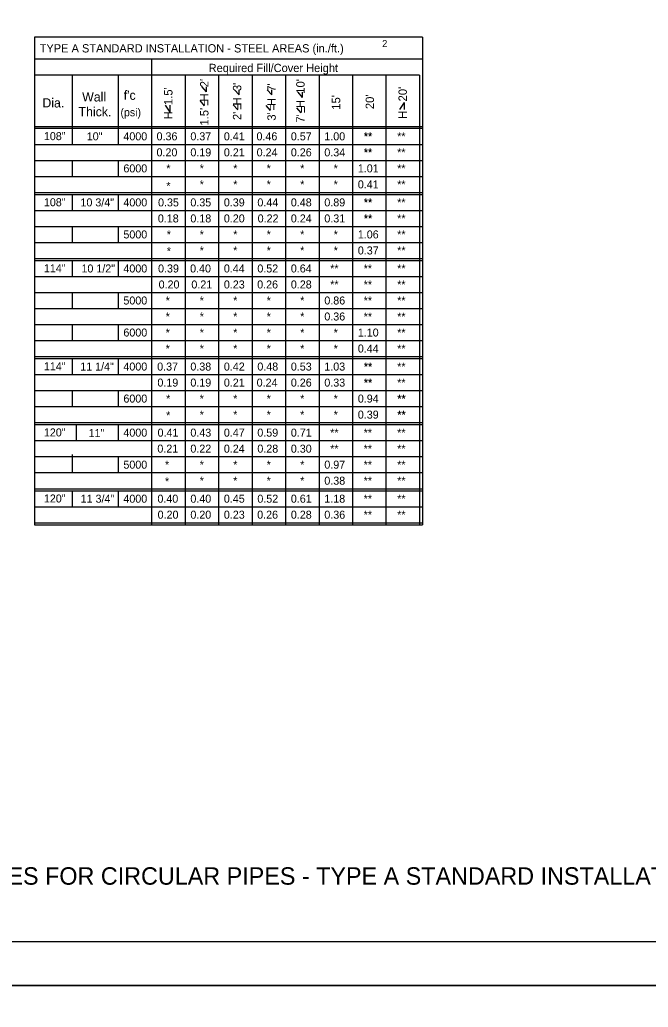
# Model space of a CAD drawing. Extents: x -22562 to -18409, y 3991 to 7171.
# Drawn here: x -20171.7 to -19955.7, y 5765.9 to 6105.3 of the extents above; entities that cross this region are included whole.
import ezdxf

# ---------------------------------------------------------------- set-up
doc = ezdxf.new("R2010")
doc.units = 0
for name, color, linetype in [('1', 7, 'Continuous'), ('2', 7, 'Continuous'), ('3', 7, 'Continuous'), ('4', 7, 'Continuous'), ('PLT-BNDY', 7, 'Continuous')]:
    doc.layers.add(name, color=color, linetype=linetype)

msp = doc.modelspace()

# ---------------------------------------------------------------- linework, layer by layer
at = {"layer": '1'}
for p, q in [((-20107.5, 6080.55), (-20109.07, 6082.32)), ((-20107.5, 6080.55), (-20107.5, 6082.3)), ((-20096.32, 6079.45), (-20097.89, 6081.22)), ((-20096.32, 6079.45), (-20096.32, 6081.21)), ((-20085.03, 6079.51), (-20086.6, 6081.27)), ((-20085.03, 6079.51), (-20085.03, 6081.26)), ((-20074.46, 6078.62), (-20076.02, 6080.38)), ((-20074.46, 6078.62), (-20074.46, 6080.37)), ((-20108.16, 6075.74), (-20109.72, 6077.51)), ((-20096.78, 6074.31), (-20098.34, 6076.08)), ((-20039.54, 6076.83), (-20041.11, 6074.41)), ((-20039.54, 6076.83), (-20039.54, 6074.43)), ((-20119.99, 6073.55), (-20121.55, 6075.97)), ((-20119.99, 6073.55), (-20119.99, 6075.96)), ((-20085.49, 6074.09), (-20087.05, 6075.86)), ((-20074.91, 6073.26), (-20076.47, 6075.02))]:
    msp.add_line(p, q, dxfattribs=at)
at = {"layer": '2'}
for p, q in [((-20166.67, 6099.37), (-20166.67, 5931.73)), ((-20033.26, 6099.37), (-20166.67, 6099.37)), ((-20033.26, 6099.37), (-20033.26, 5931.73)), ((-20033.26, 6091.8), (-20166.67, 6091.8)), ((-20126.39, 6091.8), (-20126.39, 5931.73)), ((-20034.3, 6086.29), (-20166.67, 6086.29)), ((-20153.72, 6086.29), (-20153.72, 6062.48)), ((-20137.9, 6086.29), (-20137.9, 6062.48)), ((-20114.88, 6086.29), (-20114.88, 5931.73)), ((-20103.36, 6086.29), (-20103.36, 5931.73)), ((-20091.85, 6086.29), (-20091.85, 5931.73)), ((-20080.34, 6086.29), (-20080.34, 5931.73)), ((-20068.83, 6086.29), (-20068.83, 5931.73)), ((-20057.32, 6086.29), (-20057.32, 5931.73)), ((-20045.81, 6086.29), (-20045.81, 5931.73)), ((-20034.3, 6086.29), (-20034.3, 5931.73)), ((-20166.67, 6068.67), (-20033.26, 6068.67)), ((-20166.67, 6067.99), (-20033.26, 6067.99)), ((-20153.72, 6067.99), (-20153.72, 6062.48)), ((-20137.9, 6067.99), (-20137.9, 6062.48)), ((-20166.67, 6062.48), (-20033.26, 6062.48)), ((-20166.67, 6056.98), (-20033.26, 6056.98)), ((-20153.72, 6056.98), (-20153.72, 6051.47)), ((-20137.9, 6056.98), (-20137.9, 6051.47)), ((-20166.67, 6051.47), (-20033.26, 6051.47)), ((-20166.67, 6045.97), (-20033.26, 6045.97)), ((-20166.67, 6045.97), (-20033.26, 6045.97)), ((-20166.67, 6045.28), (-20033.26, 6045.28)), ((-20153.72, 6045.28), (-20153.72, 6039.77)), ((-20137.9, 6045.28), (-20137.9, 6039.77)), ((-20166.67, 6039.77), (-20033.26, 6039.77)), ((-20166.67, 6034.27), (-20033.26, 6034.27)), ((-20153.72, 6034.27), (-20153.72, 6028.76)), ((-20137.9, 6034.27), (-20137.9, 6028.76)), ((-20166.67, 6028.76), (-20033.26, 6028.76)), ((-20166.67, 6023.26), (-20033.26, 6023.26)), ((-20166.67, 6023.26), (-20033.26, 6023.26)), ((-20166.67, 6022.57), (-20033.26, 6022.57)), ((-20153.72, 6022.57), (-20153.72, 6017.07)), ((-20137.9, 6022.57), (-20137.9, 6017.07)), ((-20166.67, 6017.07), (-20033.26, 6017.07)), ((-20166.67, 6011.56), (-20033.26, 6011.56)), ((-20153.72, 6011.56), (-20153.72, 6006.05)), ((-20137.9, 6011.56), (-20137.9, 6006.05)), ((-20166.67, 6006.05), (-20033.26, 6006.05)), ((-20166.67, 6000.55), (-20033.26, 6000.55)), ((-20153.72, 6000.55), (-20153.72, 5995.04)), ((-20137.9, 6000.55), (-20137.9, 5995.04)), ((-20166.67, 5995.04), (-20033.26, 5995.04)), ((-20166.67, 5989.54), (-20033.26, 5989.54)), ((-20166.67, 5989.54), (-20033.26, 5989.54)), ((-20166.67, 5988.85), (-20033.26, 5988.85)), ((-20153.72, 5988.85), (-20153.72, 5983.35)), ((-20137.9, 5988.85), (-20137.9, 5983.35)), ((-20166.67, 5983.35), (-20033.26, 5983.35)), ((-20166.67, 5977.84), (-20033.26, 5977.84)), ((-20153.72, 5977.84), (-20153.72, 5972.33)), ((-20137.9, 5977.84), (-20137.9, 5972.33)), ((-20166.67, 5972.33), (-20033.26, 5972.33)), ((-20166.67, 5966.83), (-20033.26, 5966.83)), ((-20166.67, 5966.14), (-20033.26, 5966.14)), ((-20152.29, 5966.14), (-20152.29, 5960.64)), ((-20137.9, 5966.14), (-20137.9, 5960.64)), ((-20166.67, 5960.64), (-20033.26, 5960.64)), ((-20166.67, 5955.13), (-20033.26, 5955.13)), ((-20153.72, 5955.82), (-20153.72, 5949.63)), ((-20137.9, 5955.13), (-20137.9, 5949.63)), ((-20166.67, 5949.63), (-20033.26, 5949.63)), ((-20166.67, 5944.12), (-20033.26, 5944.12)), ((-20166.67, 5943.43), (-20033.26, 5943.43)), ((-20153.72, 5943.43), (-20153.72, 5937.93)), ((-20137.9, 5943.43), (-20137.9, 5937.93)), ((-20166.67, 5937.93), (-20033.26, 5937.93)), ((-20166.67, 5932.42), (-20033.26, 5932.42)), ((-20166.67, 5932.42), (-20033.26, 5932.42)), ((-20166.67, 5931.73), (-20033.26, 5931.73)), ((-19558.85, 5788.37), (-20344.85, 5788.37))]:
    msp.add_line(p, q, dxfattribs=at)
at = {"layer": 'PLT-BNDY'}
for points in [[(-20384.85, 6367.37), (-19543.85, 6367.37), (-19543.85, 5773.37), (-20384.85, 5773.37)], [(-20384.85, 5773.37), (-19543.85, 5773.37), (-19543.85, 5179.37), (-20384.85, 5179.37)]]:
    msp.add_lwpolyline(points, close=True, dxfattribs=at)

# ---------------------------------------------------------------- texts
at = {"layer": '1'}
for s, height, p in [("f'c", 3.172, (-20135.95, 6077.78)), ('Thick.', 3.172, (-20151.48, 6072.12)), ('(psi)', 2.719, (-20137.07, 6072.14)), ('108"', 2.751, (-20163.39, 6063.92)), ('108"', 2.751, (-20163.39, 6041.21)), ('114"', 2.751, (-20163.39, 6018.51)), ('114"', 2.751, (-20163.39, 5984.79)), ('120"', 2.751, (-20163.39, 5962.08)), ('**', 2.751, (-20064.99, 5962.01)), ('**', 2.751, (-20053.48, 5962.01)), ('**', 2.751, (-20041.97, 5962.01)), ('**', 2.751, (-20064.99, 5956.5)), ('**', 2.751, (-20053.48, 5956.5)), ('**', 2.751, (-20041.97, 5956.5)), ('**', 2.751, (-20053.48, 5951)), ('**', 2.751, (-20041.97, 5951)), ('**', 2.751, (-20053.48, 5945.49)), ('**', 2.751, (-20041.97, 5945.49)), ('120"', 2.751, (-20163.39, 5939.37)), ('**', 2.751, (-20053.48, 5939.3)), ('**', 2.751, (-20041.97, 5939.3)), ('**', 2.751, (-20053.48, 5933.8)), ('**', 2.751, (-20041.97, 5933.8))]:
    msp.add_text(s, height=height, dxfattribs=at).set_placement(p)
for s, height, p in [("20'", 2.883, (-20049.93, 6074.58)), ('=', 2.88, (-20106.21, 6075.71)), ('=', 2.88, (-20094.83, 6074.28)), ('=', 2.88, (-20083.54, 6074.07)), ("15'", 2.883, (-20061.54, 6074.38)), ('=', 2.88, (-20072.96, 6073.23))]:
    msp.add_text(s, height=height, rotation=90, dxfattribs=at).set_placement(p)
at = {"layer": '2'}
for s, height, p in [('TYPE A STANDARD INSTALLATION - STEEL AREAS (in./ft.)', 2.8357, (-20164.84, 6094.07)), ('2', 2.42, (-20047.15, 6095.91)), ('Required Fill/Cover Height', 2.8357, (-20106.76, 6087.32)), ('DESIGN TABLES FOR CIRCULAR PIPES - TYPE A STANDARD INSTALLATION', 6, (-20228.97, 5807.99))]:
    msp.add_text(s, height=height, dxfattribs=at).set_placement(p)
at = {"layer": '3'}
for s, height, p in [('0.36', 2.753, (-20124.66, 6063.86)), ('0.37', 2.753, (-20113.04, 6063.86)), ('0.41', 2.753, (-20101.53, 6063.86)), ('0.46', 2.753, (-20090.32, 6063.86)), ('0.57', 2.753, (-20078.51, 6063.86)), ('1.00', 2.753, (-20067, 6063.86)), ('**', 2.751, (-20053.47, 6063.86)), ('**', 2.753, (-20053.35, 6063.86)), ('**', 2.751, (-20041.96, 6063.86)), ('0.20', 2.753, (-20124.68, 6058.35)), ('0.19', 2.753, (-20113.04, 6058.35)), ('0.21', 2.753, (-20101.53, 6058.35)), ('0.24', 2.753, (-20090.26, 6058.35)), ('0.26', 2.753, (-20078.51, 6058.35)), ('0.34', 2.753, (-20067, 6058.35)), ('**', 2.751, (-20053.47, 6058.35)), ('**', 2.753, (-20053.35, 6058.35)), ('**', 2.751, (-20041.96, 6058.35)), ('1.01', 2.753, (-20055.49, 6052.84)), ('*', 2.75, (-20121.31, 6052.84)), ('*', 2.75, (-20109.83, 6052.84)), ('*', 2.75, (-20098.32, 6052.84)), ('*', 2.75, (-20086.81, 6052.84)), ('*', 2.75, (-20075.3, 6052.84)), ('*', 2.75, (-20063.79, 6052.84)), ('**', 2.751, (-20041.96, 6052.84)), ('*', 2.75, (-20121.31, 6046.8)), ('*', 2.75, (-20109.83, 6047.34)), ('*', 2.75, (-20098.32, 6047.34)), ('*', 2.75, (-20086.81, 6047.34)), ('*', 2.75, (-20075.3, 6047.34)), ('*', 2.75, (-20063.79, 6047.34)), ('0.41', 2.753, (-20055.49, 6047.34)), ('**', 2.751, (-20041.96, 6047.34)), ('0.35', 2.753, (-20124.15, 6041.15)), ('0.35', 2.753, (-20113.04, 6041.15)), ('0.39', 2.753, (-20101.53, 6041.15)), ('0.44', 2.753, (-20090.01, 6041.15)), ('0.48', 2.753, (-20078.51, 6041.15)), ('0.89', 2.753, (-20067, 6041.15)), ('**', 2.751, (-20053.47, 6041.15)), ('**', 2.753, (-20053.35, 6041.15)), ('**', 2.751, (-20041.96, 6041.15)), ('0.18', 2.753, (-20124.22, 6035.64)), ('0.18', 2.753, (-20113.04, 6035.64)), ('0.20', 2.753, (-20101.53, 6035.64)), ('0.22', 2.753, (-20089.92, 6035.64)), ('0.24', 2.753, (-20078.51, 6035.64)), ('0.31', 2.753, (-20067, 6035.64)), ('**', 2.751, (-20053.47, 6035.64)), ('**', 2.753, (-20053.35, 6035.64)), ('**', 2.751, (-20041.96, 6035.64)), ('*', 2.75, (-20121.16, 6030.14)), ('*', 2.75, (-20109.83, 6030.14)), ('*', 2.75, (-20098.32, 6030.14)), ('*', 2.75, (-20086.81, 6030.14)), ('*', 2.75, (-20075.3, 6030.14)), ('*', 2.75, (-20063.79, 6030.14)), ('1.06', 2.753, (-20055.49, 6030.14)), ('**', 2.751, (-20041.96, 6030.14)), ('*', 2.75, (-20121.16, 6024.39)), ('*', 2.75, (-20109.83, 6024.63)), ('*', 2.75, (-20098.32, 6024.63)), ('*', 2.75, (-20086.81, 6024.63)), ('*', 2.75, (-20075.3, 6024.63)), ('*', 2.75, (-20063.79, 6024.63)), ('0.37', 2.753, (-20055.49, 6024.63)), ('**', 2.751, (-20041.96, 6024.63)), ('0.39', 2.753, (-20124.15, 6018.44)), ('0.40', 2.753, (-20113.13, 6018.44)), ('0.44', 2.753, (-20101.53, 6018.44)), ('0.52', 2.753, (-20090.02, 6018.44)), ('0.64', 2.753, (-20078.51, 6018.44)), ('**', 2.751, (-20064.98, 6018.44)), ('**', 2.751, (-20053.47, 6018.44)), ('**', 2.751, (-20041.96, 6018.44)), ('0.20', 2.753, (-20123.95, 6012.94)), ('0.21', 2.753, (-20112.7, 6012.94)), ('0.23', 2.753, (-20101.53, 6012.94)), ('0.26', 2.753, (-20090.08, 6012.94)), ('0.28', 2.753, (-20078.51, 6012.94)), ('**', 2.751, (-20064.98, 6012.94)), ('**', 2.751, (-20053.47, 6012.93)), ('**', 2.751, (-20041.96, 6012.93)), ('*', 2.75, (-20121.53, 6007.43)), ('*', 2.75, (-20109.83, 6007.43)), ('*', 2.75, (-20098.32, 6007.43)), ('*', 2.75, (-20086.81, 6007.43)), ('*', 2.75, (-20075.3, 6007.43)), ('0.86', 2.753, (-20067, 6007.43)), ('**', 2.751, (-20053.47, 6007.43)), ('**', 2.751, (-20041.96, 6007.43)), ('0.36', 2.753, (-20067, 6001.93)), ('*', 2.75, (-20121.53, 6001.93)), ('*', 2.75, (-20109.83, 6001.93)), ('*', 2.75, (-20098.32, 6001.93)), ('*', 2.75, (-20086.81, 6001.93)), ('*', 2.75, (-20075.3, 6001.93)), ('**', 2.751, (-20053.47, 6001.92)), ('**', 2.751, (-20041.96, 6001.92)), ('*', 2.75, (-20121.53, 5996.42)), ('*', 2.75, (-20109.83, 5996.42)), ('*', 2.75, (-20098.32, 5996.42)), ('*', 2.75, (-20086.81, 5996.42)), ('*', 2.75, (-20075.3, 5996.42)), ('*', 2.75, (-20063.79, 5996.42)), ('1.10', 2.753, (-20055.49, 5996.42)), ('**', 2.751, (-20041.96, 5996.42)), ('*', 2.75, (-20121.53, 5990.92)), ('*', 2.75, (-20109.83, 5990.92)), ('*', 2.75, (-20098.32, 5990.92)), ('*', 2.75, (-20086.81, 5990.92)), ('*', 2.75, (-20075.3, 5990.92)), ('*', 2.75, (-20063.79, 5990.92)), ('0.44', 2.753, (-20055.49, 5990.92)), ('**', 2.751, (-20041.96, 5990.91)), ('0.37', 2.753, (-20124.45, 5984.72)), ('0.38', 2.753, (-20113.04, 5984.72)), ('0.42', 2.753, (-20101.53, 5984.72)), ('0.48', 2.753, (-20090.02, 5984.72)), ('0.53', 2.753, (-20078.51, 5984.72)), ('1.03', 2.753, (-20067, 5984.72)), ('**', 2.751, (-20053.47, 5984.72)), ('**', 2.753, (-20053.35, 5984.72)), ('**', 2.753, (-20053.35, 5984.72)), ('**', 2.751, (-20041.96, 5984.72)), ('0.19', 2.753, (-20124.37, 5979.21)), ('0.19', 2.753, (-20113.04, 5979.21)), ('0.21', 2.753, (-20101.53, 5979.21)), ('0.24', 2.753, (-20090.26, 5979.21)), ('0.26', 2.753, (-20078.51, 5979.21)), ('0.33', 2.753, (-20067, 5979.21)), ('**', 2.751, (-20053.47, 5979.21)), ('**', 2.753, (-20053.35, 5979.21)), ('**', 2.753, (-20053.35, 5979.21)), ('**', 2.751, (-20041.96, 5979.21)), ('*', 2.75, (-20121.38, 5973.71)), ('*', 2.75, (-20109.83, 5973.71)), ('*', 2.75, (-20098.32, 5973.71)), ('*', 2.75, (-20086.81, 5973.71)), ('*', 2.75, (-20075.3, 5973.71)), ('*', 2.75, (-20063.79, 5973.71)), ('0.94', 2.753, (-20055.49, 5973.71)), ('**', 2.753, (-20041.84, 5973.71)), ('*', 2.75, (-20109.83, 5968.2)), ('*', 2.75, (-20098.32, 5968.2)), ('*', 2.75, (-20086.81, 5968.2)), ('*', 2.75, (-20075.3, 5968.2)), ('*', 2.75, (-20063.79, 5968.2)), ('0.39', 2.753, (-20055.49, 5968.2)), ('**', 2.753, (-20041.84, 5968.2)), ('*', 2.75, (-20121.38, 5967.97)), ('0.41', 2.753, (-20124.32, 5962.01)), ('0.43', 2.753, (-20113.04, 5962.01)), ('0.47', 2.753, (-20101.53, 5962.01)), ('0.59', 2.753, (-20090.03, 5962.01)), ('0.71', 2.753, (-20078.51, 5962.01)), ('0.21', 2.753, (-20124.39, 5956.5)), ('0.22', 2.753, (-20113.04, 5956.5)), ('0.24', 2.753, (-20101.53, 5956.5)), ('0.28', 2.753, (-20090.02, 5956.5)), ('0.30', 2.753, (-20078.51, 5956.5)), ('0.97', 2.753, (-20067, 5951)), ('*', 2.75, (-20121.76, 5951)), ('*', 2.75, (-20109.83, 5951)), ('*', 2.75, (-20098.32, 5951)), ('*', 2.75, (-20086.81, 5951)), ('*', 2.75, (-20075.3, 5951)), ('*', 2.75, (-20121.76, 5945.26)), ('*', 2.75, (-20109.83, 5945.49)), ('*', 2.75, (-20098.32, 5945.49)), ('*', 2.75, (-20086.81, 5945.49)), ('*', 2.75, (-20075.3, 5945.49)), ('0.38', 2.753, (-20067, 5945.49)), ('0.40', 2.753, (-20124.37, 5939.3)), ('0.40', 2.753, (-20113.04, 5939.3)), ('0.45', 2.753, (-20101.53, 5939.3)), ('0.52', 2.753, (-20090.02, 5939.3)), ('0.61', 2.753, (-20078.51, 5939.3)), ('1.18', 2.753, (-20067, 5939.3)), ('0.20', 2.753, (-20124.3, 5933.8)), ('0.20', 2.753, (-20113.04, 5933.8)), ('0.23', 2.753, (-20101.53, 5933.8)), ('0.26', 2.753, (-20090.08, 5933.8)), ('0.28', 2.753, (-20078.51, 5933.8)), ('0.36', 2.753, (-20067, 5933.8))]:
    msp.add_text(s, height=height, dxfattribs=at).set_placement(p)
for rotation, p in [(0.7078, (-20041.96, 5973.69)), (0.2583, (-20041.96, 5968.19))]:
    msp.add_text('**', height=2.751, rotation=rotation, dxfattribs=at).set_placement(p)
at = {"layer": '4'}
for s, height, p in [("1.5'  H  2'", 2.8834, (-20106.82, 6068.93)), ("2'  H  3'", 2.883, (-20095.54, 6070.83)), ("3'  H  7'", 2.883, (-20083.7, 6070.62)), ("7'  H  10'", 2.883, (-20073.77, 6069.94)), ("H  1.5'", 2.883, (-20119.2, 6071.07)), ("H   20'", 2.883, (-20038.63, 6071.24))]:
    msp.add_text(s, height=height, rotation=90, dxfattribs=at).set_placement(p)
for s, height, p in [('Wall', 3.172, (-20150.24, 6077.21)), ('Dia.', 3.172, (-20163.92, 6075.16)), ('10"', 2.753, (-20148.66, 6063.86)), ('4000', 2.753, (-20136.06, 6063.86)), ('6000', 2.753, (-20136.06, 6052.84)), ('10 3/4"', 2.751, (-20150.82, 6041.15)), ('4000', 2.753, (-20136.06, 6041.15)), ('5000', 2.753, (-20136.06, 6030.14)), ('10 1/2"', 2.751, (-20150.47, 6018.44)), ('4000', 2.753, (-20136.06, 6018.44)), ('5000', 2.753, (-20136.06, 6007.43)), ('6000', 2.753, (-20136.06, 5996.42)), ('11 1/4"', 2.751, (-20150.89, 5984.72)), ('4000', 2.753, (-20136.06, 5984.72)), ('6000', 2.753, (-20136.06, 5973.71)), ('11"', 2.753, (-20148.04, 5961.86)), ('4000', 2.753, (-20136.06, 5962.01)), ('5000', 2.753, (-20136.06, 5951)), ('11 3/4"', 2.751, (-20150.75, 5939.3)), ('4000', 2.753, (-20136.06, 5939.3))]:
    msp.add_text(s, height=height, dxfattribs=at).set_placement(p)

doc.saveas('drawing.dxf')
